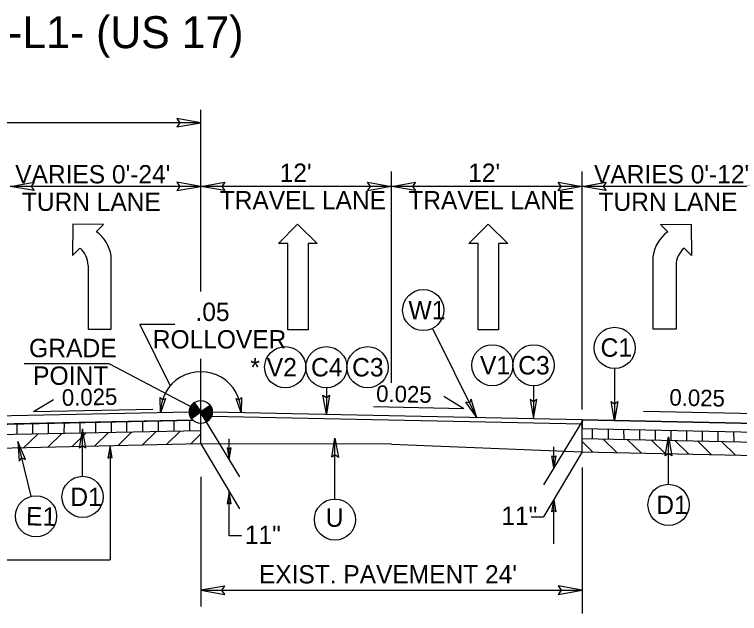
# Model space of a CAD drawing. Extents: x 2176024 to 2177225, y 75947 to 76635.
# Drawn here: x 2176794.12 to 2176839.74, y 76541.06 to 76578.77 of the extents above; entities that cross this region are included whole.
import ezdxf

# ---------------------------------------------------------------- set-up
doc = ezdxf.new("R2010")
doc.units = 0
for name, color, linetype in [('Exist XS Ground Line', 7, 'Continuous'), ('Old_Level_1', 7, 'Continuous'), ('Old_Level_11', 7, 'Continuous'), ('Old_Level_4', 7, 'Continuous'), ('Prop Dimension', 7, 'Continuous'), ('Prop Lane Arrow CELL', 7, 'Continuous'), ('Typical Curb CELL', 7, 'Continuous'), ('Typical Grade Point Symbol CELL', 7, 'Continuous'), ('Typical Pavement Slope CELL', 7, 'Continuous'), ('Typical Pavement Slope Information CELL', 7, 'Continuous'), ('Typical Shoulder Slope CELL', 7, 'Continuous'), ('Typical Slope Point Local CELL', 7, 'Continuous'), ('Typical Terminator CELL', 7, 'Continuous'), ('Typical Text General CELL', 7, 'Continuous'), ('Typical Text Label CELL', 7, 'Continuous')]:
    doc.layers.add(name, color=color, linetype=linetype)

msp = doc.modelspace()

# ---------------------------------------------------------------- linework, layer by layer
at = {"layer": 'Exist XS Ground Line'}
for q in [(2176805.841, 76551.737), (2176829.841, 76551.237)]:
    msp.add_line((2176817.841, 76551.721), q, dxfattribs=at)
at = {"layer": 'Old_Level_1'}
for p, q in [((2176795.264, 76552.349), (2176795.27, 76553.018)), ((2176796.253, 76552.367), (2176796.259, 76553.039)), ((2176797.25, 76552.39), (2176797.256, 76553.06)), ((2176798.24, 76552.413), (2176798.245, 76553.08)), ((2176799.229, 76552.434), (2176799.234, 76553.101)), ((2176800.21, 76552.455), (2176800.215, 76553.121)), ((2176801.189, 76552.473), (2176801.195, 76553.142)), ((2176802.186, 76552.494), (2176802.192, 76553.162)), ((2176803.174, 76552.516), (2176803.179, 76553.183)), ((2176804.163, 76552.53), (2176804.169, 76553.204)), ((2176805.153, 76552.55), (2176805.158, 76553.224)), ((2176794.275, 76552.326), (2176794.281, 76552.998)), ((2176830.496, 76552.05), (2176830.491, 76552.699)), ((2176831.502, 76552.025), (2176831.497, 76552.678)), ((2176832.476, 76552.013), (2176832.471, 76552.658)), ((2176833.466, 76551.984), (2176833.46, 76552.638)), ((2176834.463, 76551.977), (2176834.457, 76552.617)), ((2176835.442, 76551.956), (2176835.437, 76552.596)), ((2176836.423, 76551.936), (2176836.418, 76552.576)), ((2176794.664, 76551.463), (2176795.576, 76552.359)), ((2176796.184, 76551.501), (2176797.084, 76552.384)), ((2176797.722, 76551.552), (2176798.607, 76552.423)), ((2176799.15, 76551.587), (2176800.023, 76552.445)), ((2176800.618, 76551.624), (2176801.485, 76552.477)), ((2176802.155, 76551.655), (2176803.024, 76552.51)), ((2176803.679, 76551.695), (2176804.54, 76552.542)), ((2176805.188, 76551.728), (2176805.841, 76552.37)), ((2176837.412, 76551.911), (2176837.407, 76552.555)), ((2176838.401, 76551.892), (2176838.396, 76552.535)), ((2176839.399, 76551.869), (2176839.393, 76552.514)), ((2176830.512, 76551.223), (2176829.843, 76551.881)), ((2176832.022, 76551.186), (2176831.155, 76552.038)), ((2176833.57, 76551.147), (2176832.702, 76552.002)), ((2176835.069, 76551.132), (2176834.205, 76551.982)), ((2176836.527, 76551.105), (2176835.669, 76551.948)), ((2176837.957, 76551.068), (2176837.091, 76551.92)), ((2176839.493, 76551.018), (2176838.61, 76551.885))]:
    msp.add_line(p, q, dxfattribs=at)
at = {"layer": 'Old_Level_11'}
for p, q in [((2176804.207, 76559.249), (2176801.999, 76559.249)), ((2176801.999, 76559.249), (2176803.911, 76555.393)), ((2176820.415, 76559.003), (2176823.21, 76553.389)), ((2176794.722, 76556.791), (2176800.053, 76556.791)), ((2176800.053, 76556.791), (2176805.841, 76553.751)), ((2176831.884, 76556.486), (2176831.884, 76553.208)), ((2176826.782, 76555.393), (2176826.782, 76553.327)), ((2176813.743, 76555.268), (2176813.743, 76553.603)), ((2176798.4, 76549.696), (2176798.4, 76552.692)), ((2176835.273, 76549.196), (2176835.273, 76552.192)), ((2176795.164, 76548.436), (2176794.318, 76551.879)), ((2176814.282, 76548.268), (2176814.282, 76552.098))]:
    msp.add_line(p, q, dxfattribs=at)
for points in [[(2176813.949, 76554.803), (2176813.743, 76553.603), (2176813.529, 76554.81), (2176813.743, 76554.657)], [(2176822.49, 76554.371), (2176823.21, 76553.389), (2176822.863, 76554.564), (2176822.74, 76554.332)], [(2176826.575, 76554.527), (2176826.782, 76553.327), (2176826.995, 76554.534), (2176826.782, 76554.381)], [(2176832.091, 76554.408), (2176831.884, 76553.208), (2176831.671, 76554.415), (2176831.884, 76554.262)], [(2176798.607, 76551.492), (2176798.4, 76552.692), (2176798.187, 76551.486), (2176798.4, 76551.639)], [(2176835.066, 76550.992), (2176835.273, 76552.192), (2176835.486, 76550.986), (2176835.273, 76551.139)], [(2176794.808, 76550.764), (2176794.318, 76551.879), (2176794.402, 76550.657), (2176794.572, 76550.857)], [(2176814.076, 76550.898), (2176814.282, 76552.098), (2176814.496, 76550.891), (2176814.282, 76551.045)]]:
    msp.add_lwpolyline(points, close=True, dxfattribs=at)
for centre in [(2176819.838, 76560.163), (2176831.884, 76557.782), (2176811.151, 76556.564), (2176813.743, 76556.564), (2176816.335, 76556.564), (2176824.19, 76556.689), (2176826.782, 76556.689), (2176798.4, 76548.4), (2176835.273, 76547.9), (2176795.473, 76547.178), (2176814.282, 76546.972)]:
    msp.add_circle(centre, 1.296, dxfattribs=at)
msp.add_arc((2176805.841, 76553.751), 2.534, 358.8065, 181.1935, dxfattribs=at)
at = {"layer": 'Old_Level_4'}
for p, q in [((2176810.727, 76564.355), (2176811.929, 76565.577)), ((2176811.929, 76565.577), (2176813.171, 76564.355)), ((2176822.717, 76564.355), (2176823.92, 76565.577)), ((2176823.92, 76565.577), (2176825.162, 76564.355)), ((2176811.309, 76564.355), (2176810.727, 76564.355)), ((2176811.309, 76558.923), (2176811.309, 76564.355)), ((2176813.171, 76564.355), (2176812.589, 76564.355)), ((2176812.589, 76564.355), (2176812.589, 76558.923)), ((2176823.299, 76564.355), (2176822.717, 76564.355)), ((2176823.299, 76558.923), (2176823.299, 76564.355)), ((2176825.162, 76564.355), (2176824.58, 76564.355)), ((2176824.58, 76564.355), (2176824.58, 76558.923)), ((2176812.589, 76558.923), (2176811.309, 76558.923)), ((2176824.58, 76558.923), (2176823.299, 76558.923))]:
    msp.add_line(p, q, dxfattribs=at)
at = {"layer": 'Prop Dimension'}
for p, q in [((2176805.841, 76561.333), (2176805.841, 76572.767)), ((2176805.841, 76571.958), (2176745.841, 76571.958)), ((2176817.841, 76555.591), (2176817.841, 76568.884)), ((2176829.841, 76553.9), (2176829.841, 76568.884)), ((2176805.841, 76567.947), (2176793.841, 76567.947)), ((2176817.841, 76567.947), (2176805.841, 76567.947)), ((2176829.841, 76567.947), (2176817.841, 76567.947)), ((2176841.841, 76567.947), (2176829.841, 76567.947)), ((2176805.841, 76553.751), (2176805.841, 76557.094)), ((2176805.796, 76553.738), (2176808.266, 76549.656)), ((2176829.886, 76553.238), (2176827.416, 76549.156)), ((2176805.841, 76551.737), (2176808.266, 76547.642)), ((2176807.629, 76550.731), (2176807.629, 76552.059)), ((2176800.129, 76551.606), (2176800.129, 76544.435)), ((2176829.841, 76551.237), (2176827.416, 76547.142)), ((2176828.052, 76550.231), (2176828.052, 76551.559)), ((2176829.841, 76550.241), (2176829.841, 76541.058)), ((2176805.841, 76549.662), (2176805.841, 76541.498)), ((2176807.629, 76545.941), (2176807.629, 76548.717)), ((2176828.052, 76545.441), (2176828.052, 76548.217)), ((2176826.636, 76547.142), (2176827.416, 76547.142)), ((2176808.409, 76545.941), (2176807.629, 76545.941)), ((2176793.298, 76544.435), (2176800.129, 76544.435)), ((2176805.841, 76542.523), (2176829.841, 76542.523))]:
    msp.add_line(p, q, dxfattribs=at)
at = {"layer": 'Prop Lane Arrow CELL'}
for p, q in [((2176797.794, 76565.577), (2176797.775, 76563.602)), ((2176799.725, 76565.559), (2176797.794, 76565.577)), ((2176799.265, 76565.097), (2176799.725, 76565.559)), ((2176834.773, 76565.559), (2176836.703, 76565.577)), ((2176835.233, 76565.097), (2176834.773, 76565.559)), ((2176836.703, 76565.577), (2176836.722, 76563.602)), ((2176797.775, 76563.602), (2176798.235, 76564.064)), ((2176836.722, 76563.602), (2176836.262, 76564.064)), ((2176800.198, 76558.956), (2176800.189, 76563.585)), ((2176834.3, 76558.956), (2176834.308, 76563.585)), ((2176798.742, 76562.968), (2176798.749, 76558.953)), ((2176835.755, 76562.968), (2176835.748, 76558.953)), ((2176798.749, 76558.953), (2176800.198, 76558.956)), ((2176835.748, 76558.953), (2176834.3, 76558.956))]:
    msp.add_line(p, q, dxfattribs=at)
for centre, radius, start, end in [((2176797.919, 76563.233), 2.305, 8.7824, 54.0941), ((2176836.579, 76563.233), 2.305, 125.9059, 171.2176), ((2176797.312, 76562.97), 1.437, 0.1063, 49.7645), ((2176837.185, 76562.97), 1.437, 130.2355, 179.8937)]:
    msp.add_arc(centre, radius, start, end, dxfattribs=at)
at = {"layer": 'Typical Curb CELL'}
for p, q in [((2176805.841, 76551.737), (2176805.841, 76553.751)), ((2176829.841, 76551.237), (2176829.841, 76553.251))]:
    msp.add_line(p, q, dxfattribs=at)
at = {"layer": 'Typical Grade Point Symbol CELL'}
for p, q in [((2176805.429, 76554.343), (2176805.841, 76553.751)), ((2176805.841, 76553.751), (2176806.432, 76554.163)), ((2176805.248, 76553.341), (2176805.841, 76553.751)), ((2176805.841, 76553.751), (2176805.248, 76553.341)), ((2176806.253, 76553.159), (2176805.841, 76553.751))]:
    msp.add_line(p, q, dxfattribs=at)
for points in [[(2176805.596, 76554.103), (2176805.12, 76553.772)], [(2176805.604, 76554.092), (2176805.12, 76553.755)], [(2176805.612, 76554.08), (2176805.12, 76553.738)], [(2176805.587, 76554.115), (2176805.121, 76553.79)], [(2176805.62, 76554.068), (2176805.121, 76553.72)], [(2176805.629, 76554.056), (2176805.121, 76553.703)], [(2176805.579, 76554.127), (2176805.122, 76553.809)], [(2176805.637, 76554.044), (2176805.123, 76553.686)], [(2176805.571, 76554.139), (2176805.124, 76553.828)], [(2176805.645, 76554.032), (2176805.124, 76553.67)], [(2176805.563, 76554.151), (2176805.126, 76553.847)], [(2176805.653, 76554.021), (2176805.126, 76553.654)], [(2176805.554, 76554.163), (2176805.128, 76553.866)], [(2176805.661, 76554.009), (2176805.129, 76553.638)], [(2176805.546, 76554.174), (2176805.132, 76553.886)], [(2176805.67, 76553.997), (2176805.132, 76553.623)], [(2176805.678, 76553.985), (2176805.135, 76553.607)], [(2176805.538, 76554.186), (2176805.137, 76553.907)], [(2176805.686, 76553.973), (2176805.138, 76553.592)], [(2176805.694, 76553.961), (2176805.141, 76553.576)], [(2176805.53, 76554.198), (2176805.142, 76553.928)], [(2176805.703, 76553.95), (2176805.145, 76553.562)], [(2176805.521, 76554.21), (2176805.148, 76553.95)], [(2176805.711, 76553.938), (2176805.149, 76553.547)], [(2176805.513, 76554.222), (2176805.154, 76553.972)], [(2176805.719, 76553.926), (2176805.154, 76553.532)], [(2176805.505, 76554.234), (2176805.162, 76553.995)], [(2176805.497, 76554.245), (2176805.171, 76554.018)], [(2176805.489, 76554.257), (2176805.181, 76554.043)], [(2176805.48, 76554.269), (2176805.194, 76554.07)], [(2176805.472, 76554.281), (2176805.208, 76554.097)], [(2176805.464, 76554.293), (2176805.225, 76554.126)], [(2176805.456, 76554.305), (2176805.244, 76554.157)], [(2176805.447, 76554.316), (2176805.271, 76554.194)], [(2176805.439, 76554.328), (2176805.305, 76554.235)], [(2176805.431, 76554.34), (2176805.366, 76554.295)], [(2176806.436, 76554.157), (2176806.436, 76554.157), (2176805.844, 76553.746)], [(2176806.444, 76554.146), (2176805.853, 76553.734)], [(2176806.451, 76554.133), (2176805.861, 76553.722)], [(2176806.46, 76554.121), (2176805.869, 76553.71)], [(2176806.466, 76554.108), (2176805.877, 76553.698)], [(2176806.473, 76554.096), (2176805.886, 76553.687)], [(2176806.48, 76554.083), (2176805.894, 76553.675)], [(2176806.487, 76554.07), (2176805.902, 76553.663)], [(2176806.494, 76554.057), (2176805.91, 76553.651)], [(2176806.5, 76554.044), (2176805.919, 76553.639)], [(2176806.505, 76554.03), (2176805.927, 76553.627)], [(2176806.511, 76554.016), (2176805.935, 76553.616)], [(2176806.517, 76554.003), (2176805.943, 76553.604)], [(2176806.521, 76553.988), (2176805.952, 76553.592)], [(2176806.526, 76553.974), (2176805.96, 76553.58)], [(2176806.531, 76553.96), (2176805.968, 76553.568)], [(2176806.535, 76553.945), (2176805.976, 76553.556)], [(2176806.539, 76553.931), (2176805.984, 76553.545)], [(2176805.727, 76553.914), (2176805.159, 76553.519)], [(2176805.736, 76553.902), (2176805.164, 76553.504)], [(2176805.744, 76553.89), (2176805.169, 76553.491)], [(2176805.752, 76553.879), (2176805.175, 76553.477)], [(2176805.76, 76553.867), (2176805.18, 76553.463)], [(2176805.769, 76553.855), (2176805.186, 76553.45)], [(2176805.777, 76553.843), (2176805.193, 76553.437)], [(2176805.785, 76553.831), (2176805.199, 76553.423)], [(2176805.793, 76553.819), (2176805.206, 76553.41)], [(2176805.801, 76553.808), (2176805.212, 76553.398)], [(2176805.81, 76553.796), (2176805.219, 76553.385)], [(2176805.818, 76553.784), (2176805.228, 76553.373)], [(2176805.826, 76553.772), (2176805.235, 76553.36)], [(2176805.834, 76553.76), (2176805.243, 76553.348), (2176805.243, 76553.348)], [(2176806.542, 76553.915), (2176805.993, 76553.533)], [(2176806.545, 76553.9), (2176806.001, 76553.521)], [(2176806.548, 76553.884), (2176806.009, 76553.509)], [(2176806.551, 76553.869), (2176806.017, 76553.497)], [(2176806.554, 76553.853), (2176806.026, 76553.485)], [(2176806.556, 76553.837), (2176806.034, 76553.474)], [(2176806.558, 76553.82), (2176806.042, 76553.462)], [(2176806.559, 76553.804), (2176806.05, 76553.45)], [(2176806.561, 76553.788), (2176806.059, 76553.438)], [(2176806.561, 76553.77), (2176806.067, 76553.426)], [(2176806.562, 76553.753), (2176806.075, 76553.414)], [(2176806.561, 76553.735), (2176806.083, 76553.403)], [(2176806.561, 76553.717), (2176806.092, 76553.391)], [(2176806.56, 76553.699), (2176806.1, 76553.379)], [(2176806.558, 76553.68), (2176806.108, 76553.367)], [(2176806.555, 76553.661), (2176806.116, 76553.355)], [(2176806.553, 76553.642), (2176806.124, 76553.343)], [(2176806.55, 76553.622), (2176806.133, 76553.332)], [(2176806.546, 76553.602), (2176806.141, 76553.32)], [(2176806.541, 76553.581), (2176806.149, 76553.308)], [(2176806.535, 76553.559), (2176806.157, 76553.296)], [(2176806.529, 76553.537), (2176806.166, 76553.284)], [(2176806.521, 76553.514), (2176806.174, 76553.272)], [(2176806.512, 76553.49), (2176806.182, 76553.261)], [(2176806.502, 76553.466), (2176806.19, 76553.249)], [(2176806.491, 76553.44), (2176806.199, 76553.237)], [(2176806.478, 76553.414), (2176806.207, 76553.225)], [(2176806.461, 76553.384), (2176806.215, 76553.213)], [(2176806.442, 76553.353), (2176806.223, 76553.201)], [(2176806.417, 76553.319), (2176806.232, 76553.19)], [(2176806.384, 76553.278), (2176806.24, 76553.178)], [(2176806.332, 76553.224), (2176806.248, 76553.166)]]:
    msp.add_lwpolyline(points, dxfattribs=at)
msp.add_circle((2176805.841, 76553.752), 0.721, dxfattribs=at)
for start, end in [(124.8249, 214.8249), (304.8249, 34.8249)]:
    msp.add_arc((2176805.841, 76553.752), 0.721, start, end, dxfattribs=at)
at = {"layer": 'Typical Pavement Slope CELL'}
for p, q in [((2176805.841, 76553.751), (2176805.841, 76553.501)), ((2176806.511, 76553.487), (2176829.841, 76553.001)), ((2176805.345, 76553.228), (2176789.841, 76552.905)), ((2176829.841, 76552.713), (2176841.841, 76552.463)), ((2176805.841, 76551.737), (2176786.947, 76551.305)), ((2176829.841, 76552.069), (2176841.841, 76551.819))]:
    msp.add_line(p, q, dxfattribs=at)
at = {"layer": 'Typical Pavement Slope Information CELL'}
for p, q in [((2176795.311, 76553.771), (2176796.572, 76554.533)), ((2176822.394, 76553.953), (2176821.133, 76554.715)), ((2176822.394, 76553.953), (2176816.709, 76554.067)), ((2176795.311, 76553.771), (2176802.817, 76553.921)), ((2176841.2, 76553.633), (2176833.694, 76553.783))]:
    msp.add_line(p, q, dxfattribs=at)
at = {"layer": 'Typical Shoulder Slope CELL'}
for p, q in [((2176805.841, 76552.569), (2176789.841, 76552.236)), ((2176829.841, 76551.237), (2176841.841, 76550.987))]:
    msp.add_line(p, q, dxfattribs=at)
at = {"layer": 'Typical Slope Point Local CELL'}
for p, q in [((2176805.121, 76553.703), (2176805.121, 76553.703)), ((2176805.126, 76553.654), (2176805.126, 76553.654)), ((2176805.141, 76553.576), (2176805.141, 76553.577)), ((2176805.145, 76553.562), (2176805.145, 76553.562)), ((2176805.154, 76553.532), (2176805.154, 76553.533)), ((2176806.511, 76553.487), (2176829.841, 76553.001)), ((2176806.521, 76553.514), (2176806.521, 76553.514)), ((2176806.529, 76553.537), (2176806.529, 76553.537)), ((2176806.541, 76553.581), (2176806.541, 76553.58)), ((2176806.546, 76553.602), (2176806.545, 76553.601)), ((2176806.55, 76553.622), (2176806.55, 76553.622)), ((2176806.553, 76553.642), (2176806.553, 76553.642)), ((2176806.56, 76553.699), (2176806.559, 76553.699)), ((2176829.841, 76553.251), (2176806.561, 76553.736)), ((2176806.561, 76553.717), (2176806.561, 76553.717)), ((2176805.186, 76553.45), (2176805.186, 76553.45)), ((2176805.199, 76553.423), (2176805.199, 76553.423)), ((2176805.206, 76553.41), (2176805.206, 76553.41)), ((2176805.212, 76553.398), (2176805.213, 76553.398)), ((2176805.219, 76553.385), (2176805.22, 76553.385)), ((2176805.235, 76553.36), (2176805.235, 76553.361)), ((2176805.243, 76553.348), (2176805.243, 76553.349)), ((2176805.249, 76553.34), (2176805.248, 76553.341)), ((2176805.248, 76553.341), (2176805.248, 76553.341)), ((2176829.841, 76553.251), (2176841.841, 76553.001)), ((2176841.841, 76553.001), (2176829.841, 76553.251)), ((2176829.841, 76553.251), (2176829.841, 76552.713)), ((2176829.841, 76553.001), (2176829.841, 76553.251)), ((2176829.841, 76552.713), (2176841.841, 76552.463))]:
    msp.add_line(p, q, dxfattribs=at)
for points in [[(2176805.12, 76553.736), (2176789.841, 76553.418), (2176789.841, 76552.905), (2176805.345, 76553.228)], [(2176805.121, 76553.703), (2176805.121, 76553.703)], [(2176805.126, 76553.654), (2176805.126, 76553.654)], [(2176805.141, 76553.576), (2176805.141, 76553.576)], [(2176805.145, 76553.562), (2176805.145, 76553.562)], [(2176805.154, 76553.532), (2176805.154, 76553.532)], [(2176806.521, 76553.514), (2176806.521, 76553.514)], [(2176806.529, 76553.537), (2176806.529, 76553.537)], [(2176806.541, 76553.581), (2176806.541, 76553.581)], [(2176806.546, 76553.602), (2176806.546, 76553.602)], [(2176806.55, 76553.622), (2176806.55, 76553.622)], [(2176806.553, 76553.642), (2176806.553, 76553.642)], [(2176806.559, 76553.699), (2176806.56, 76553.699)], [(2176806.561, 76553.717), (2176806.561, 76553.717)], [(2176805.186, 76553.45), (2176805.186, 76553.45)], [(2176805.199, 76553.423), (2176805.199, 76553.423)], [(2176805.206, 76553.41), (2176805.206, 76553.41)], [(2176805.213, 76553.398), (2176805.212, 76553.398)], [(2176805.22, 76553.385), (2176805.219, 76553.385)], [(2176805.235, 76553.361), (2176805.235, 76553.36)], [(2176805.243, 76553.349), (2176805.243, 76553.348)]]:
    msp.add_lwpolyline(points, dxfattribs=at)
for start, end in [(181.2559, 183.8761), (183.8895, 185.2021), (185.2021, 186.5121), (186.5121, 187.8094), (187.8245, 189.0767), (189.0767, 191.5882), (191.5882, 192.8361), (192.8361, 194.0754), (194.0907, 195.2968), (195.2976, 197.7127), (197.7154, 200.0946), (200.0946, 204.7878), (338.4481, 340.731), (340.7368, 342.6429), (342.646, 346.2404), (346.2648, 347.9455), (347.9775, 349.598), (349.5984, 351.2038), (351.2196, 352.7539), (352.7539, 354.2837), (354.2837, 355.7778), (355.8127, 357.2394), (358.6425, 358.745), (357.2652, 358.6425), (204.7881, 207.109), (207.1121, 208.2646), (208.2653, 209.4175), (209.4186, 210.5682), (210.5718, 211.7158), (211.7158, 212.8649), (212.8666, 214.0118), (214.0122, 214.7719), (214.8249, 226.5883)]:
    msp.add_arc((2176805.841, 76553.752), 0.721, start, end, dxfattribs=at)
at = {"layer": 'Typical Terminator CELL'}
for points in [[(2176804.331, 76571.698), (2176805.841, 76571.958), (2176804.323, 76572.226), (2176804.516, 76571.958)], [(2176795.35, 76567.687), (2176793.841, 76567.947), (2176795.359, 76568.215), (2176795.166, 76567.947)], [(2176804.331, 76567.687), (2176805.841, 76567.947), (2176804.323, 76568.215), (2176804.516, 76567.947)], [(2176807.35, 76567.687), (2176805.841, 76567.947), (2176807.359, 76568.215), (2176807.166, 76567.947)], [(2176816.331, 76568.207), (2176817.841, 76567.947), (2176816.323, 76567.678), (2176816.516, 76567.947)], [(2176819.35, 76567.687), (2176817.841, 76567.947), (2176819.359, 76568.215), (2176819.166, 76567.947)], [(2176828.331, 76568.207), (2176829.841, 76567.947), (2176828.323, 76567.678), (2176828.516, 76567.947)], [(2176831.35, 76567.687), (2176829.841, 76567.947), (2176831.359, 76568.215), (2176831.166, 76567.947)], [(2176803.609, 76554.6), (2176803.307, 76553.698), (2176803.286, 76554.655), (2176803.432, 76554.512)], [(2176808.397, 76554.649), (2176808.374, 76553.698), (2176808.072, 76554.606), (2176808.254, 76554.512)], [(2176800.259, 76550.851), (2176800.129, 76551.606), (2176799.995, 76550.847), (2176800.129, 76550.944)], [(2176807.497, 76551.485), (2176807.629, 76550.731), (2176807.761, 76551.49), (2176807.627, 76551.393)], [(2176828.185, 76550.985), (2176828.052, 76550.231), (2176827.921, 76550.99), (2176828.054, 76550.893)], [(2176807.761, 76547.963), (2176807.629, 76548.717), (2176807.497, 76547.958), (2176807.631, 76548.055)], [(2176827.92, 76547.463), (2176828.052, 76548.217), (2176828.184, 76547.458), (2176828.05, 76547.555)], [(2176807.35, 76542.783), (2176805.841, 76542.523), (2176807.359, 76542.255), (2176807.166, 76542.523)], [(2176828.331, 76542.263), (2176829.841, 76542.523), (2176828.323, 76542.792), (2176828.516, 76542.523)]]:
    msp.add_lwpolyline(points, close=True, dxfattribs=at)

# ---------------------------------------------------------------- texts
at = {"layer": 'Old_Level_11'}
for s, rotation, p in [('W1', 359.9997, (2176818.906, 76559.583)), ('GRADE', 359.9998, (2176795.031, 76557.195)), ('C1', 0.0003, (2176830.995, 76557.224)), ('* V2', 0.0003, (2176808.956, 76555.984)), ('C4', 0.0003, (2176812.776, 76555.984)), ('C3', 0.0003, (2176815.362, 76555.984)), ('V1', 359.9997, (2176823.409, 76556.109)), ('C3', 359.9997, (2176825.814, 76556.109)), ('POINT', 359.9998, (2176795.284, 76555.455)), ('D1', 0.0003, (2176797.627, 76547.82)), ('D1', 0.0003, (2176834.5, 76547.32)), ('E1', 358.8249, (2176794.833, 76546.611)), ('U', 0.0003, (2176813.696, 76546.518))]:
    msp.add_text(s, height=1.16, rotation=rotation, dxfattribs=at).set_placement(p)
for p in [(2176824.754, 76546.641), (2176808.613, 76545.441)]:
    msp.add_text('11"', height=1.1533, dxfattribs=at).set_placement(p)
at = {"layer": 'Typical Pavement Slope Information CELL'}
for rotation, p in [(358.8543, (2176816.867, 76554.386)), (1.1457, (2176797.107, 76554.129)), (358.8543, (2176835.32, 76554.151))]:
    msp.add_text('0.025', height=1.0429, rotation=rotation, dxfattribs=at).set_placement(p)
at = {"layer": 'Typical Text General CELL'}
for s, height, p in [("VARIES 0'-24'", 1.15334, (2176794.163, 76568.139)), ("12' ", 1.1533, (2176810.803, 76568.235)), ("12' ", 1.1533, (2176822.668, 76568.235)), ("VARIES 0'-12'", 1.15334, (2176830.586, 76568.139)), ('TRAVEL LANE', 1.15334, (2176807.033, 76566.505)), ('TRAVEL LANE', 1.15334, (2176818.899, 76566.505)), (' TURN LANE', 1.1533, (2176794.154, 76566.409)), (' TURN LANE', 1.1533, (2176830.439, 76566.409)), ("EXIST. PAVEMENT 24'", 1.15334, (2176809.498, 76542.951))]:
    msp.add_text(s, height=height, dxfattribs=at).set_placement(p)
for s, p in [('.05', (2176805.505, 76559.476)), ('ROLLOVER', (2176802.82, 76557.746))]:
    msp.add_text(s, height=1.1533, rotation=360, dxfattribs=at).set_placement(p)
at = {"layer": 'Typical Text Label CELL'}
msp.add_text('C -L- (US 17) & -L1- (US 17)', height=2.01314, dxfattribs=at).set_placement((2176774.42, 76576.654))

doc.saveas('drawing.dxf')
